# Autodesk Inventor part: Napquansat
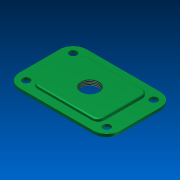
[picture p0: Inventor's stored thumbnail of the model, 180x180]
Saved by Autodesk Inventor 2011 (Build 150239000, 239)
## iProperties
Created: 2011-05
Part Number: Napquansat
Document SubType Name: Modeling
Designer: 904Chiaki
Density: 1 g/cm^3
Author: 904Chiaki
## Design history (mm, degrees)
sketch "Sketch1"
  geometry: L1 (-149.664, 113.411)-(-149.664, 58.411); L2 (-124.664, 115.911)-(-124.664, 55.911); L3 (-239.664, 123.411)-(-159.664, 123.411); L4 (-159.664, 48.411)-(-239.664, 48.411); L5 (-254.664, 135.911)-(-144.664, 135.911); L6 (-144.664, 35.911)-(-254.664, 35.911); L7 (-249.664, 58.411)-(-249.664, 113.411); L8 (-274.664, 55.911)-(-274.664, 115.911); A1 r 10 centre (-159.664, 58.411) between (-159.664, 48.411) and (-149.664, 58.411); A2 r 10 centre (-159.664, 113.411) between (-149.664, 113.411) and (-159.664, 123.411); A3 r 20 centre (-144.664, 115.911) between (-124.664, 115.911) and (-144.664, 135.911); A4 r 10 centre (-239.664, 113.411) between (-239.664, 123.411) and (-249.664, 113.411); A5 r 10 centre (-239.664, 58.411) between (-249.664, 58.411) and (-239.664, 48.411); A6 r 20 centre (-254.664, 115.911) between (-254.664, 135.911) and (-274.664, 115.911); A7 r 20 centre (-254.664, 55.911) between (-274.664, 55.911) and (-254.664, 35.911); A8 r 20 centre (-144.664, 55.911) between (-144.664, 35.911) and (-124.664, 55.911); 1 further point
  constraints: 16 end point, 16 point on circle, 8 centre point
extrude "Extrusion1" new body sketch "Sketch1" distance "d0" = 4; taper "d1" = 0 deg
sketch "Sketch2"
  geometry: L1 (-149.664, 113.411)-(-149.664, 58.411) reference; L2 (-159.664, 48.411)-(-239.664, 48.411) reference; L3 (-249.664, 58.411)-(-249.664, 113.411) reference; L4 (-239.664, 123.411)-(-159.664, 123.411) reference; A1 r 10 centre (-159.664, 58.411) between (-159.664, 48.411) and (-149.664, 58.411) reference; A2 r 10 centre (-239.664, 58.411) between (-249.664, 58.411) and (-239.664, 48.411) reference; A3 r 10 centre (-239.664, 113.411) between (-239.664, 123.411) and (-249.664, 113.411) reference; A4 r 10 centre (-159.664, 113.411) between (-149.664, 113.411) and (-159.664, 123.411) reference; 1 further point
extrude "Extrusion2" join sketch "Sketch2" distance "d2" = 4; taper "d3" = 0 deg
fillet "Fillet1" dims "d4" = 2
workpoint "Work Point1"
workpoint "Work Point2"
workpoint "Work Point3"
workpoint "Work Point4"
sketch "Sketch4"
  geometry: C1 r 13.5 at (-199.664, 85.911); 1 further point
  constraints: 1 centre point
  dimensions: "d9" = 27 diameter of C1
extrude "Extrusion3" cut sketch "Sketch4" stored distance "d10" = 4; taper "d11" = 0 deg
thread "Thread1" dims "d12" = 10, "d13" = 0
node "Hole2"
sketch "Sketch6"
  geometry: L1 (149.664, 113.411)-(149.664, 58.411) reference; L2 (159.664, 48.411)-(239.664, 48.411) reference; L3 (249.664, 58.411)-(249.664, 113.411) reference; L4 (239.664, 123.411)-(159.664, 123.411) reference; C1 r 13.5 at (199.664, 85.911) reference; A1 r 10 centre (159.664, 58.411) between (149.664, 58.411) and (159.664, 48.411) reference; A2 r 10 centre (239.664, 58.411) between (239.664, 48.411) and (249.664, 58.411) reference; A3 r 10 centre (239.664, 113.411) between (249.664, 113.411) and (239.664, 123.411) reference; A4 r 10 centre (159.664, 113.411) between (159.664, 123.411) and (149.664, 113.411) reference; 1 further point
extrude "Extrusion4" join sketch "Sketch6" stored distance "d21" = 10; taper "d22" = 0 deg
body "Solid1"
sketch "Sketch5"
  geometry: 4 further points
hole "Hole1" sketch "Sketch5" diameter "d14" = 11; stored, may be unused: countersink angle "d18" = 90 deg, drill point angle "d20" = 0 deg; dims "d15" = 6, "d16" = 4, "d17" = 2, "d19" = 8
